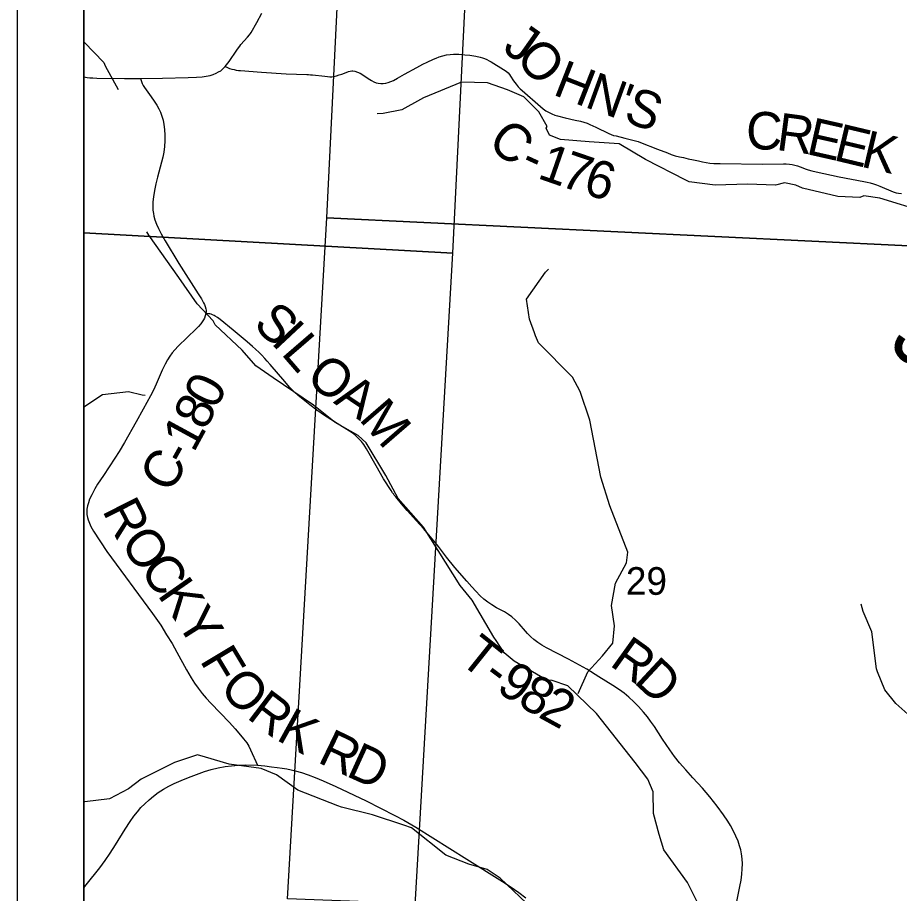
# Model space of a CAD drawing. Extents: x 0 to 34, y 0 to 22.
# Drawn here: x 23.737 to 25.071, y 18.626 to 19.951 of the extents above; entities that cross this region are included whole.
import ezdxf

# ---------------------------------------------------------------- set-up
doc = ezdxf.new("R2010")
doc.units = 0
for name, color, linetype in [('GM_X_County_Road', 7, 'Continuous'), ('GM_X_County_Road_Text', 7, 'Continuous'), ('GM_X_County_Text', 7, 'Continuous'), ('GM_X_Minor_River', 7, 'Continuous'), ('GM_X_Minor_River_Text', 7, 'Continuous'), ('GM_X_Section', 7, 'Continuous'), ('GM_X_Section_Text', 7, 'Continuous'), ('GM_X_State_Shield', 7, 'Continuous'), ('GM_X_Township_Road', 7, 'Continuous'), ('GM_X_Township_Road_Text', 7, 'Continuous'), ('SH_Cut_Line', 7, 'Continuous'), ('SH_Data', 7, 'Continuous')]:
    doc.layers.add(name, color=color, linetype=linetype)

msp = doc.modelspace()

# ---------------------------------------------------------------- linework, layer by layer
at = {"layer": 'GM_X_County_Road'}
for points in [[(23.9231, 19.8589), (23.9563, 19.8596), (23.9951, 19.8603), (24.0081, 19.8608), (24.0166, 19.8615), (24.0226, 19.8624), (24.0285, 19.8637), (24.0331, 19.8652), (24.0376, 19.867), (24.0414, 19.8689), (24.0445, 19.8708), (24.0478, 19.8734), (24.0515, 19.877), (24.0574, 19.8846), (24.0689, 19.9019), (24.0713, 19.9054), (24.0733, 19.9081), (24.0751, 19.9105), (24.0851, 19.9216), (24.0881, 19.9251), (24.0895, 19.9269), (24.0906, 19.9286), (24.0993, 19.9439), (24.1068, 19.9581)], [(24.0515, 19.877), (24.0548, 19.8755), (24.0579, 19.8743), (24.0615, 19.8732), (24.0647, 19.8724), (24.068, 19.8718), (24.0713, 19.8713), (24.0745, 19.871), (24.1064, 19.8685), (24.1436, 19.8662), (24.1747, 19.865), (24.1775, 19.8649), (24.1804, 19.8647), (24.1834, 19.8645), (24.2022, 19.8623), (24.2059, 19.862), (24.2094, 19.8617), (24.2129, 19.8617), (24.2163, 19.8621), (24.2199, 19.863), (24.2239, 19.8643), (24.2279, 19.8656), (24.232, 19.8672), (24.2377, 19.8694), (24.2406, 19.8703), (24.2429, 19.8707), (24.2446, 19.8707), (24.2476, 19.8701), (24.2516, 19.8687), (24.2555, 19.8668), (24.2597, 19.8643), (24.2678, 19.8588), (24.2726, 19.8558), (24.2764, 19.8538), (24.28, 19.8526), (24.283, 19.8519), (24.2868, 19.8515), (24.2905, 19.8515), (24.2943, 19.852), (24.298, 19.8529), (24.3021, 19.8543), (24.3061, 19.8562), (24.312, 19.8596), (24.3228, 19.8656), (24.3413, 19.8758), (24.3506, 19.8808), (24.3567, 19.8838), (24.3663, 19.8881), (24.3707, 19.8899), (24.3753, 19.8917), (24.3807, 19.8934), (24.386, 19.8947), (24.3915, 19.8955), (24.397, 19.8957), (24.405, 19.8956), (24.4137, 19.895), (24.4216, 19.8942), (24.4304, 19.8928), (24.437, 19.8914), (24.4405, 19.8904), (24.4438, 19.8892), (24.4472, 19.8877), (24.4506, 19.8859), (24.4539, 19.884), (24.4724, 19.8728), (24.4765, 19.8699), (24.4794, 19.8675), (24.4816, 19.8648), (24.4831, 19.8626), (24.4878, 19.8553), (24.4915, 19.8503), (24.4948, 19.8466), (24.4979, 19.8434), (24.5007, 19.841), (24.5284, 19.8164), (24.5325, 19.8129), (24.5365, 19.81), (24.5406, 19.8078), (24.5458, 19.8055), (24.5501, 19.8037), (24.5539, 19.8023), (24.5659, 19.7994), (24.5807, 19.796), (24.5888, 19.7942), (24.5939, 19.7929), (24.5988, 19.7913), (24.601, 19.7905), (24.6031, 19.7896), (24.6123, 19.7852), (24.6316, 19.7756), (24.6352, 19.7742), (24.639, 19.7729), (24.6427, 19.772), (24.6561, 19.7688), (24.672, 19.7647), (24.6762, 19.7636), (24.6799, 19.7622), (24.7057, 19.752), (24.7204, 19.7463), (24.726, 19.7442), (24.7323, 19.7421), (24.7389, 19.7404), (24.7447, 19.7392), (24.7521, 19.7376), (24.7599, 19.7359), (24.7677, 19.7342), (24.7736, 19.7328), (24.7791, 19.7318), (24.7845, 19.7309), (24.7908, 19.7304), (24.8005, 19.7302), (24.8644, 19.7294), (24.8961, 19.7299), (24.9004, 19.7299), (24.9053, 19.7295), (24.9095, 19.7288), (24.9131, 19.728), (24.9173, 19.7269), (24.9214, 19.7254), (24.9252, 19.7239), (24.929, 19.7225), (24.9333, 19.7209), (24.9389, 19.7192), (24.9454, 19.7176), (24.9802, 19.7103), (25.0177, 19.7029), (25.0225, 19.702), (25.0271, 19.7009), (25.0323, 19.6994), (25.037, 19.6979), (25.0417, 19.696), (25.0619, 19.6876), (25.0665, 19.6861), (25.0704, 19.6853), (25.0745, 19.6847)], [(23.8372, 19.8617), (23.8373, 19.8616), (23.8423, 19.8607), (23.8467, 19.8602), (23.8511, 19.8598), (23.8571, 19.8594), (23.8987, 19.859), (23.9231, 19.8589)], [(23.9231, 19.8589), (23.9258, 19.8516), (23.9274, 19.8484), (23.9293, 19.8454), (23.9393, 19.8313), (23.944, 19.8245), (23.9477, 19.8188), (23.9508, 19.813), (23.9533, 19.8079), (23.9555, 19.8018), (23.9572, 19.7957), (23.9586, 19.7893), (23.9596, 19.782), (23.9601, 19.7732), (23.9601, 19.7647), (23.9594, 19.7563), (23.9583, 19.7473), (23.9569, 19.7398), (23.9488, 19.7098), (23.9462, 19.6995), (23.9443, 19.6897), (23.9427, 19.6799), (23.9419, 19.6725), (23.9417, 19.6662), (23.9419, 19.6599), (23.9426, 19.6549), (23.9434, 19.6506), (23.9449, 19.6452), (23.9472, 19.6386), (23.9502, 19.6318), (23.9542, 19.624), (23.9603, 19.6131), (23.9811, 19.5792), (24.0106, 19.5332), (24.0154, 19.5253), (24.017, 19.5225), (24.0187, 19.5193), (24.0199, 19.5168), (24.0211, 19.5137), (24.0221, 19.5106), (24.0223, 19.5084), (24.0224, 19.5061), (24.0222, 19.5034), (24.0212, 19.4998), (24.0198, 19.4964), (24.0184, 19.4936), (24.0164, 19.4905), (24.0144, 19.4876), (24.0107, 19.4835), (24.0073, 19.4801), (23.9801, 19.4538), (23.9749, 19.4483), (23.9713, 19.444), (23.9677, 19.4389), (23.964, 19.4331), (23.9604, 19.4265), (23.956, 19.4175), (23.9483, 19.3998), (23.9433, 19.3885), (23.9384, 19.3785), (23.9273, 19.3584), (23.9165, 19.3395), (23.8988, 19.3081), (23.891, 19.2947), (23.8844, 19.2843), (23.8672, 19.2584), (23.8583, 19.2449), (23.8542, 19.2379), (23.8494, 19.2291), (23.8462, 19.2223), (23.8442, 19.217), (23.8428, 19.2121), (23.842, 19.2071), (23.8418, 19.2039), (23.8421, 19.1989), (23.8429, 19.1945), (23.844, 19.1909), (23.8458, 19.1861), (23.8482, 19.181), (23.8522, 19.1739), (23.8723, 19.1433), (23.9413, 19.0494), (23.9537, 19.0316), (23.9627, 19.0171), (23.9709, 19.0039), (23.9783, 18.991), (23.9928, 18.9643), (24, 18.9519), (24.005, 18.944), (24.0103, 18.9363), (24.0164, 18.9284), (24.0225, 18.9212), (24.0297, 18.9134), (24.0576, 18.8844), (24.0664, 18.8747), (24.0744, 18.8653), (24.0791, 18.8595), (24.0838, 18.8538), (24.0871, 18.8486), (24.0898, 18.8429), (24.1003, 18.8199)], [(23.8372, 18.634), (23.841, 18.6388), (23.8615, 18.6645), (23.8696, 18.6754), (23.8774, 18.6865), (23.8855, 18.699), (23.9001, 18.7228), (23.9075, 18.7344), (23.9132, 18.7425), (23.9185, 18.7494), (23.9238, 18.7556), (23.9295, 18.7614), (23.936, 18.7673), (23.9427, 18.7729), (23.9499, 18.7783), (23.958, 18.7833), (23.9658, 18.7878), (23.9742, 18.7919), (23.9845, 18.7967), (23.9956, 18.8012), (24.0079, 18.8059), (24.0202, 18.8101), (24.0303, 18.813), (24.0409, 18.8155), (24.0511, 18.8177), (24.061, 18.8189), (24.0716, 18.8197), (24.0818, 18.8202), (24.1003, 18.8199)], [(24.1003, 18.8199), (24.1113, 18.8187), (24.1213, 18.8174), (24.1301, 18.8163), (24.1375, 18.8152), (24.1446, 18.814), (24.1511, 18.8127), (24.1572, 18.8113), (24.1668, 18.8085), (24.1767, 18.8054), (24.1873, 18.8013), (24.1995, 18.7962), (24.2187, 18.7877), (24.2646, 18.7656), (24.3079, 18.7434), (24.3214, 18.7363), (24.3398, 18.7257), (24.4169, 18.6777), (24.471, 18.6437), (24.4824, 18.6361), (24.4956, 18.6269), (24.506, 18.6191)]]:
    msp.add_lwpolyline(points, dxfattribs=at)
at = {"layer": 'GM_X_County_Text'}
msp.add_lwpolyline([(28.4159, 17.3358), (28.4427, 17.7695), (28.4677, 18.1732), (28.5249, 19.1245), (28.5443, 19.4375), (28.5808, 20.0106), (28.6062, 20.4055), (27.8401, 20.4449), (27.0539, 20.4845), (26.781, 20.4973), (26.0533, 20.5337), (24.4417, 20.6174), (23.8372, 20.6485), (23.8372, 14.4177)], dxfattribs=at)
at = {"layer": 'GM_X_Minor_River'}
for points in [[(23.8372, 19.9148), (23.8381, 19.9141), (23.8674, 19.8832), (23.8699, 19.8781), (23.8892, 19.8422)], [(25.1108, 19.6565), (25.042, 19.678), (25.0178, 19.6814), (25.0114, 19.6787), (24.9785, 19.6805), (24.9248, 19.6929), (24.9149, 19.6978), (24.8976, 19.7012), (24.8839, 19.6978), (24.8416, 19.6992), (24.7925, 19.6975), (24.7535, 19.7028), (24.7486, 19.705), (24.6873, 19.7364), (24.6476, 19.7603), (24.6019, 19.7632), (24.5588, 19.7669), (24.5418, 19.7733), (24.5372, 19.7836), (24.5387, 19.7862), (24.5259, 19.8086), (24.5032, 19.8314), (24.4786, 19.842), (24.4483, 19.8525), (24.409, 19.8536), (24.3512, 19.8299), (24.347, 19.8272), (24.3187, 19.8116), (24.2904, 19.8058), (24.2813, 19.8054)], [(24.778, 18.5877), (24.7511, 18.642), (24.7152, 18.6917), (24.708, 18.7148), (24.6996, 18.7464), (24.6988, 18.7794), (24.6909, 18.7984), (24.6716, 18.8238), (24.6133, 18.8978), (24.5698, 18.9399), (24.5459, 18.9478), (24.538, 18.9482), (24.4888, 18.9773), (24.4733, 18.9898), (24.4612, 19.0084), (24.4578, 19.0137), (24.4249, 19.0695), (24.4067, 19.0915), (24.3514, 19.18), (24.3128, 19.2232), (24.2943, 19.2581), (24.2647, 19.3075), (24.2523, 19.3188), (24.2178, 19.3385), (24.1849, 19.3647), (24.124, 19.4059), (24.0975, 19.4241), (24.0771, 19.4476), (24.0363, 19.4863), (24.0332, 19.492), (24.009, 19.5178), (23.981, 19.5576), (23.9359, 19.6218), (23.9325, 19.6271)], [(24.5856, 18.9283), (24.6003, 18.961), (24.6222, 18.985), (24.6379, 19.0046), (24.6406, 19.0307), (24.6359, 19.0616), (24.6418, 19.0952), (24.6586, 19.1262), (24.6606, 19.1421), (24.6333, 19.2124), (24.6198, 19.2554), (24.6032, 19.3417), (24.5886, 19.3851), (24.5768, 19.4071), (24.5255, 19.4589), (24.5209, 19.4693), (24.5195, 19.4743), (24.5118, 19.4946), (24.5071, 19.5252), (24.5359, 19.566), (24.5406, 19.5704)], [(23.8372, 19.362), (23.8658, 19.3805), (23.9052, 19.3853), (23.9255, 19.3801), (23.93, 19.3796)], [(25.1087, 18.3739), (25.0935, 18.4107), (25.0941, 18.4539), (25.1016, 18.4905), (25.1008, 18.5141), (25.09, 18.5425), (25.0891, 18.5524), (25.0973, 18.5837), (25.1038, 18.6359), (25.1116, 18.6577), (25.1078, 18.6931), (25.1074, 18.769), (25.1105, 18.8335), (25.104, 18.8694), (25.0889, 18.893), (25.0661, 18.9131), (25.0493, 18.9338), (25.0384, 18.9611), (25.0367, 18.9657), (25.0297, 19.0217), (25.0166, 19.0525), (25.0135, 19.0633)], [(24.5172, 18.6014), (24.4673, 18.6486), (24.4476, 18.6617), (24.4199, 18.6702), (24.3852, 18.6838), (24.3331, 18.725), (24.3215, 18.7291), (24.2744, 18.7447), (24.2271, 18.7561), (24.2219, 18.7582), (24.161, 18.7817), (24.1288, 18.8052), (24.1056, 18.8146), (24.0571, 18.8215), (24.0215, 18.8321), (24.0095, 18.8356), (23.9748, 18.8238), (23.9241, 18.7984), (23.9051, 18.7838), (23.8763, 18.7688), (23.8391, 18.7643), (23.8372, 18.7644)]]:
    msp.add_lwpolyline(points, dxfattribs=at)
at = {"layer": 'GM_X_Section'}
for points in [[(24.2561, 20.6827), (25.3065, 20.6239), (25.2325, 19.5985), (24.2052, 19.6482)], [(24.2052, 19.6482), (25.2325, 19.5985), (25.1763, 18.5784), (24.1456, 18.6175)]]:
    msp.add_lwpolyline(points, close=True, dxfattribs=at)
at = {"layer": 'GM_X_State_Shield'}
for points in [[(23.8372, 20.6603), (23.8372, 19.6255), (24.396, 19.5948), (24.4469, 20.6293)], [(23.8372, 19.6255), (23.8372, 18.5819), (24.3364, 18.5641), (24.396, 19.5948)]]:
    msp.add_lwpolyline(points, close=True, dxfattribs=at)
at = {"layer": 'GM_X_Township_Road'}
msp.add_lwpolyline([(24.8233, 18.6033), (24.8303, 18.636), (24.832, 18.6458), (24.8332, 18.655), (24.8338, 18.6631), (24.8339, 18.6706), (24.8335, 18.678), (24.8326, 18.6855), (24.8314, 18.6916), (24.8297, 18.6976), (24.8273, 18.7047), (24.8242, 18.7122), (24.8204, 18.7201), (24.8159, 18.7283), (24.8117, 18.7352), (24.8054, 18.7445), (24.7959, 18.7575), (24.7848, 18.7718), (24.7735, 18.785), (24.759, 18.8005), (24.7482, 18.8125), (24.739, 18.8233), (24.7313, 18.833), (24.724, 18.843), (24.7132, 18.859), (24.7008, 18.8783), (24.6951, 18.8865), (24.6903, 18.893), (24.6844, 18.9002), (24.6768, 18.9086), (24.6698, 18.9156), (24.662, 18.9228), (24.6548, 18.9287), (24.6478, 18.9339), (24.6379, 18.9404), (24.6168, 18.9536), (24.5983, 18.965), (24.571, 18.9802), (24.5373, 18.9975), (24.5304, 19.0016), (24.5244, 19.0056), (24.5185, 19.0098), (24.5136, 19.0139), (24.5086, 19.0191), (24.5027, 19.026), (24.4991, 19.0303), (24.4962, 19.0336), (24.4931, 19.0369), (24.4905, 19.0394), (24.4849, 19.0443), (24.4798, 19.0479), (24.474, 19.0516), (24.4678, 19.0548), (24.4619, 19.0578), (24.4548, 19.0622), (24.4489, 19.0664), (24.4425, 19.0712), (24.4371, 19.0763), (24.4305, 19.0829), (24.4245, 19.0895), (24.417, 19.0982), (24.3988, 19.1191), (24.3864, 19.1347), (24.3742, 19.1507), (24.3646, 19.1625), (24.3512, 19.178), (24.3407, 19.1896), (24.3265, 19.2054), (24.3181, 19.2154), (24.3093, 19.2259), (24.3072, 19.2285), (24.3059, 19.2302), (24.3046, 19.2319), (24.3022, 19.2354), (24.2909, 19.2532), (24.28, 19.2727), (24.265, 19.2985), (24.2625, 19.3025), (24.2609, 19.305), (24.2591, 19.3074), (24.2575, 19.3095), (24.2559, 19.3113), (24.2511, 19.3163), (24.2495, 19.3179), (24.2474, 19.3196), (24.2453, 19.3212), (24.2424, 19.3232), (24.2394, 19.3251), (24.2247, 19.3345), (24.2018, 19.3492), (24.19, 19.3572), (24.1795, 19.3649), (24.1692, 19.373), (24.1617, 19.3794), (24.1558, 19.3848), (24.1488, 19.3919), (24.1414, 19.4002), (24.1192, 19.4262), (24.115, 19.4311), (24.1111, 19.4354), (24.1066, 19.4403), (24.1027, 19.4442), (24.0972, 19.4495), (24.0927, 19.4536), (24.0847, 19.4604), (24.0633, 19.4783), (24.0435, 19.4941), (24.0394, 19.4971), (24.0361, 19.4994), (24.0344, 19.5004), (24.0323, 19.5014), (24.0303, 19.5021), (24.0282, 19.5027), (24.026, 19.503), (24.0222, 19.5034)], dxfattribs=at)
at = {"layer": 'SH_Cut_Line'}
msp.add_lwpolyline([(30.6372, 20.9), (23.8372, 20.9), (23.8372, 14.4177)], dxfattribs=at)
at = {"layer": 'SH_Data'}
for points in [[(23.7372, 21), (30.7372, 21), (30.7372, 14), (23.7372, 14)], [(23.8372, 20.9), (30.6372, 20.9), (30.6372, 14.1), (23.8372, 14.1)]]:
    msp.add_lwpolyline(points, close=True, dxfattribs=at)

# ---------------------------------------------------------------- texts
at = {"layer": 'GM_X_County_Road_Text'}
for s, rotation, p in [('J', 324.8161, (24.4692, 19.9012)), ('O', 312.4504, (24.4886, 19.888)), ('H', 338.6262, (24.5455, 19.8352)), ('N', 340.0241, (24.5935, 19.8164)), ('S', 339.5641, (24.6521, 19.7951)), ("'", 339.6384, (24.6404, 19.7994)), ('C', 358.3976, (24.8389, 19.7523)), ('R', 352.3609, (24.8839, 19.7511)), ('C', 320.9705, (24.446, 19.7583)), ('E', 347.2922, (24.9289, 19.7451)), ('E', 346.5843, (24.9702, 19.7358)), ('K', 346.5848, (25.0115, 19.726)), ('1', 340.8123, (24.5221, 19.7087)), ('7', 341.1906, (24.5555, 19.6971)), ('-', 335.3927, (24.4954, 19.7207)), ('6', 343.3419, (24.5909, 19.6851)), ('0', 63.2976, (24.0368, 19.3561)), ('8', 64.064, (24.0216, 19.3248)), ('1', 61.4814, (24.0036, 19.2915)), ('C', 60.0092, (23.9681, 19.2294)), ('-', 60.7424, (23.9918, 19.2705)), ('R', 296.8984, (23.8645, 19.2054)), ('O', 306.2126, (23.8909, 19.1552)), ('C', 306.2141, (23.9205, 19.1149)), ('K', 304.9152, (23.9478, 19.0775)), ('Y', 302.3796, (23.9761, 19.0371)), ('F', 300.9804, (24.012, 18.9783)), ('O', 314.0911, (24.0404, 18.9342)), ('R', 322.77, (24.0822, 18.8921)), ('K', 331.0252, (24.1268, 18.859)), ('R', 334.2692, (24.1892, 18.825)), ('D', 335.4924, (24.2324, 18.8042))]:
    msp.add_text(s, height=0.0568, rotation=rotation, dxfattribs=at).set_placement(p)
at = {"layer": 'GM_X_Minor_River_Text'}
msp.add_text("John's", height=0.09469, rotation=315.0035, dxfattribs=at).set_placement((25.0531, 19.456))
at = {"layer": 'GM_X_Section_Text'}
msp.add_text('29', height=0.04186, rotation=0, dxfattribs=at).set_placement((24.6576, 19.0776))
at = {"layer": 'GM_X_Township_Road_Text'}
for s, rotation, p in [('S', 317.4701, (24.0918, 19.4843)), ('I', 313.0871, (24.1192, 19.4592)), ('L', 310.781, (24.1347, 19.4426)), ('O', 321.6367, (24.171, 19.4023)), ('A', 325.9725, (24.2139, 19.3685)), ('M', 310.879, (24.2524, 19.3432)), ('T', 321.3342, (24.4031, 18.9769)), ('R', 324.3838, (24.6314, 18.9717)), ('9', 326.5091, (24.4595, 18.9331)), ('D', 317.1011, (24.6679, 18.9457)), ('-', 323.3227, (24.438, 18.949)), ('8', 329.4437, (24.4914, 18.9121)), ('2', 331.2715, (24.5232, 18.8933))]:
    msp.add_text(s, height=0.0568, rotation=rotation, dxfattribs=at).set_placement(p)

doc.saveas('drawing.dxf')
